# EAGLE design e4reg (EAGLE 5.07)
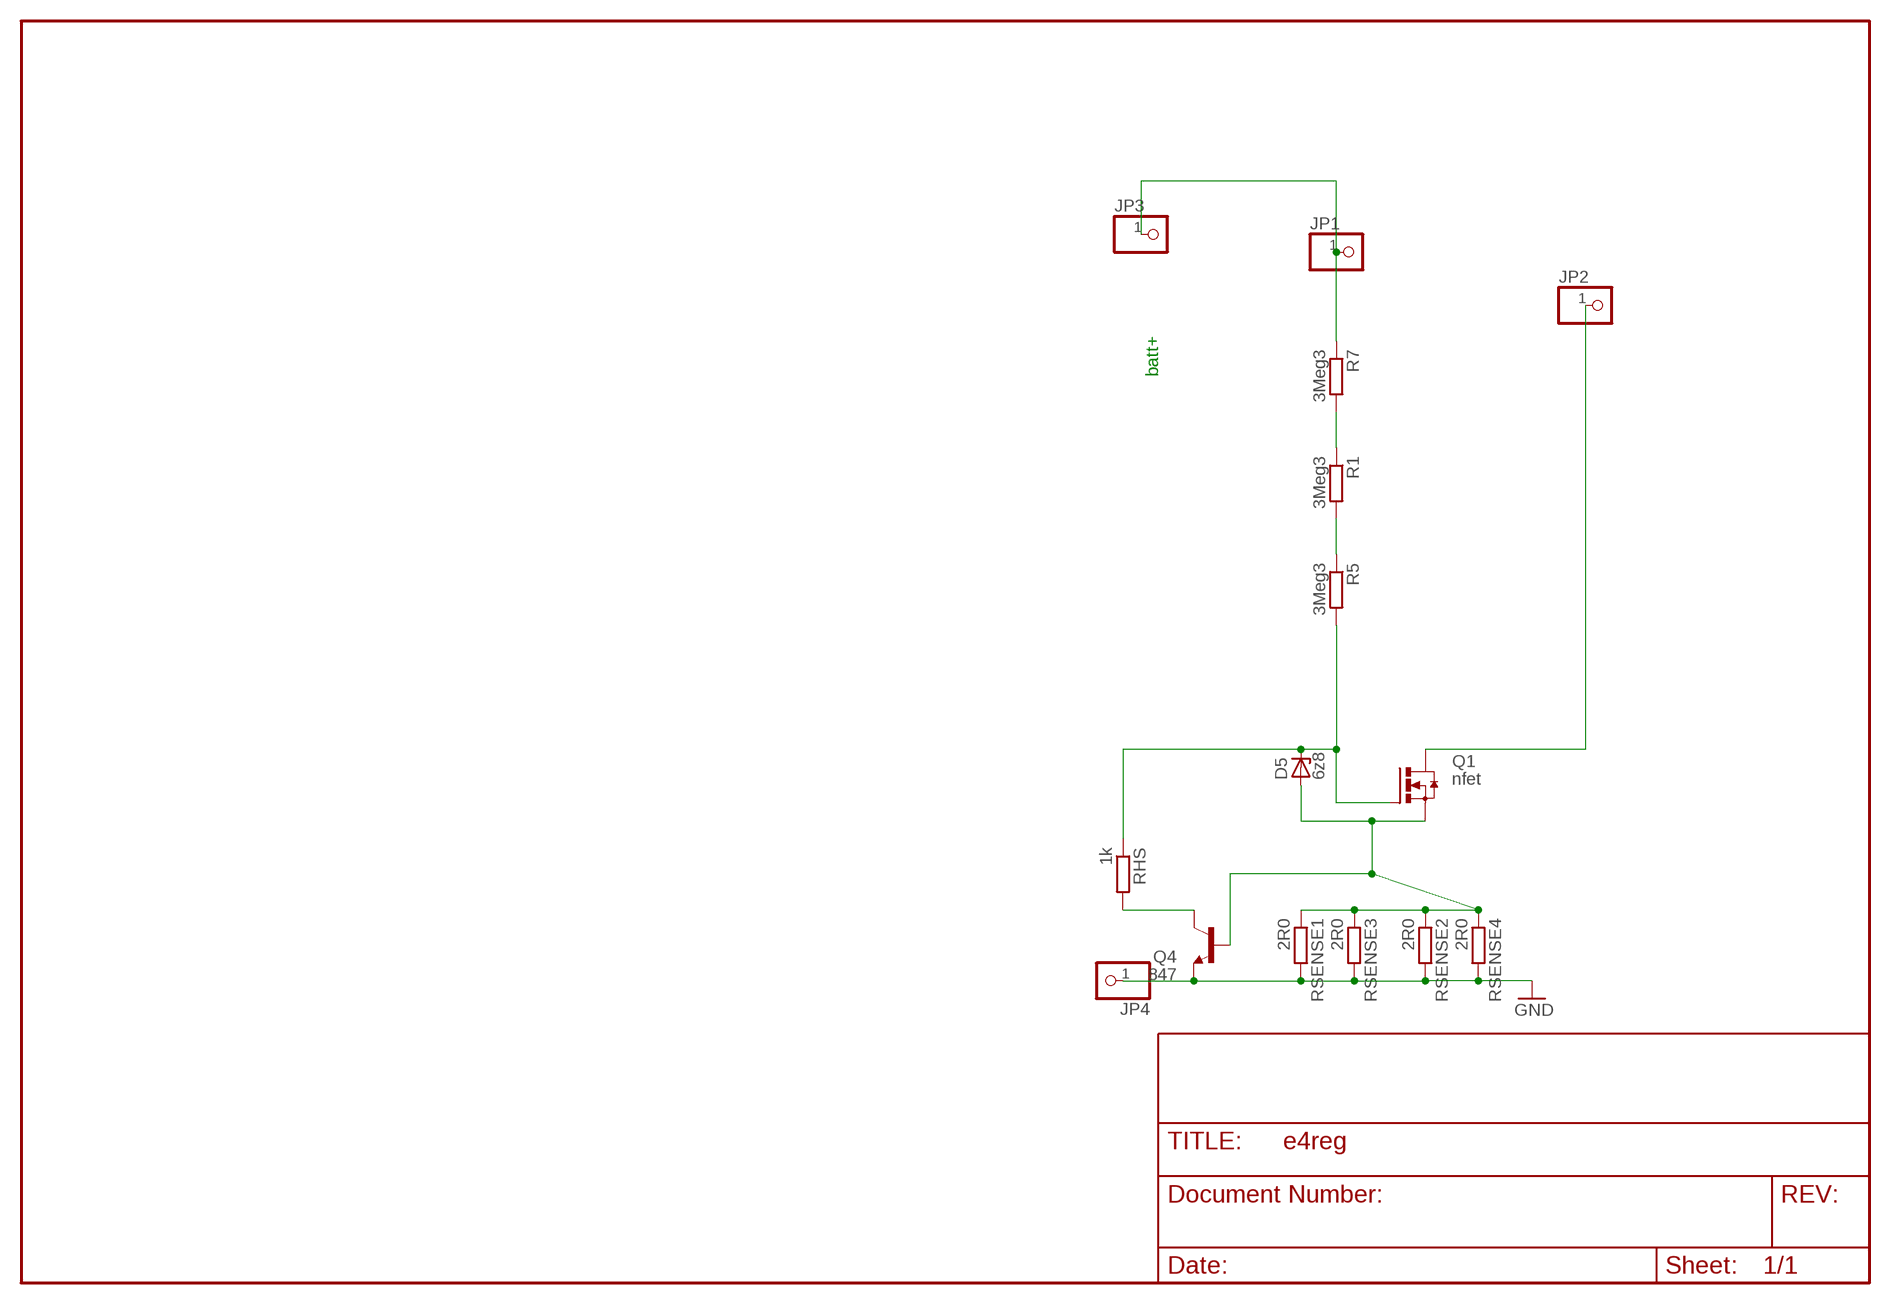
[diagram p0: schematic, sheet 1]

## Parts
D5  6z8  ZENER-DIODESOD80C  [SOD80C]
JP1  PINHD-1X11MM6  [1X1MM8]
JP2  PINHD-1X11MM6  [1X1MM8]
JP3  PINHD-1X11MM6  [1X1MM8]
JP4  PINHD-1X11MM6  [1X1MM8]
Q1  nfet  N-HEXFET_DPAK-  [TO252]
Q4  847  BC847ASMD  [SOT23]
R1  3Meg3  R-EU_R1206  [R1206]
R5  3Meg3  R-EU_R1206  [R1206]
R7  3Meg3  R-EU_R1206  [R1206]
RHS  1k  R-EU_R2512  [R2512]
RSENSE1  2R0  R-EU_R2512  [R2512]
RSENSE2  2R0  R-EU_R1210  [R1210]
RSENSE3  2R0  R-EU_R2512  [R2512]
RSENSE4  2R0  R-EU_R1210  [R1210]

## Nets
GND: JP4.1 Q4.2(E) RSENSE1.2 RSENSE2.2 RSENSE3.2 RSENSE4.2
LED-: JP2.1 Q1.3(D)
N$1: D5.C Q1.1(G) R5.2 RHS.1
N$2: R1.2 R5.1
N$4: R1.1 R7.2
N$7: Q4.3(C) RHS.2
S: D5.A Q1.2(S) Q4.1(B) RSENSE1.1 RSENSE2.1 RSENSE3.1 RSENSE4.1
VPLUS: JP1.1 JP3.1 R7.1

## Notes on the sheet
- batt+

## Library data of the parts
D5 = diode:ZENER-DIODE: Z-Diode
JP1-JP4 = pinhead:PINHD-1X1: PIN HEADER
Q1 = transistor-power:N-HEXFET_?-*: HEXFET® Power MOSFET
Q4 = transistor-npn:BC847*: NPN Transistor
R1 R5 R7 RHS RSENSE1-RSENSE4 = rcl:R-EU_: RESISTOR, European symbol

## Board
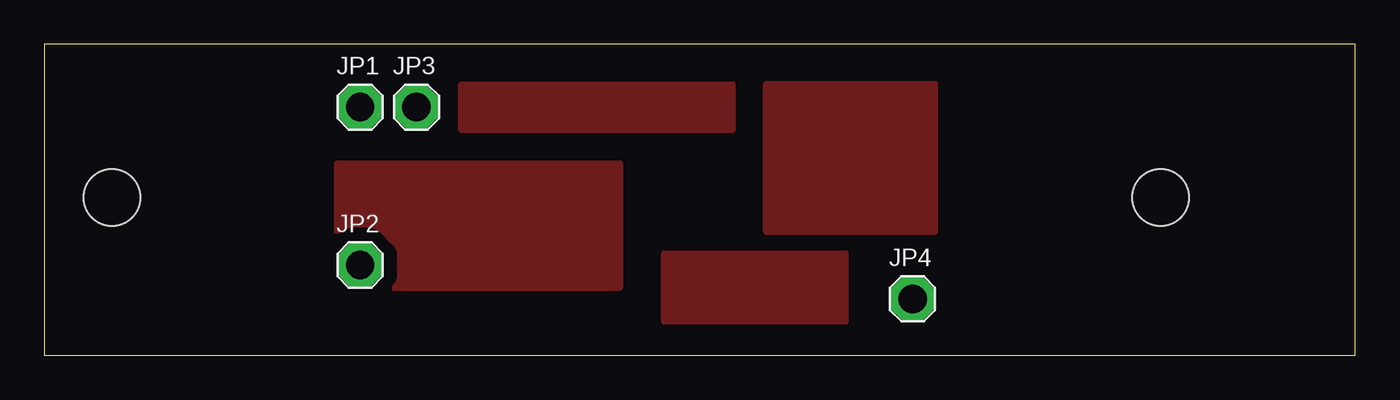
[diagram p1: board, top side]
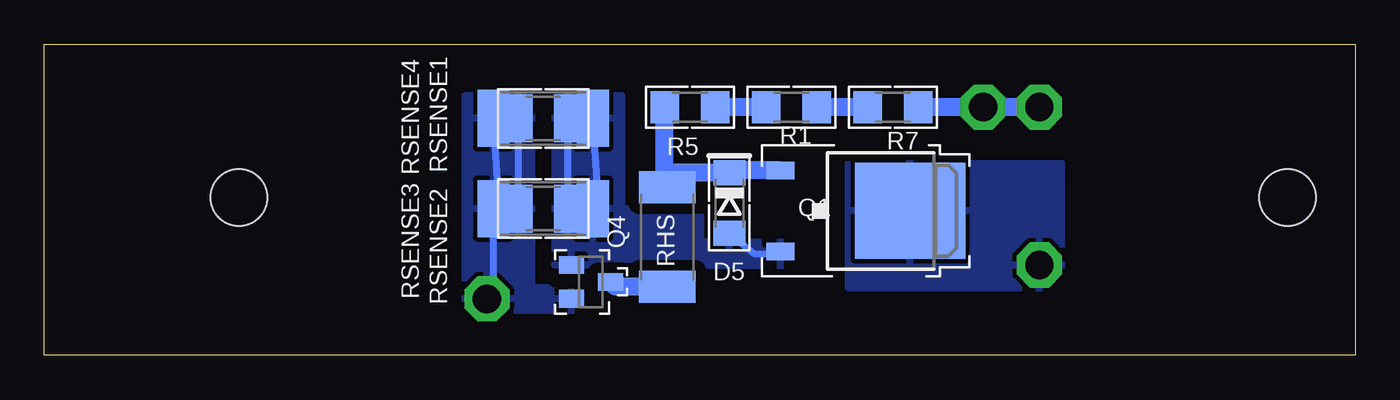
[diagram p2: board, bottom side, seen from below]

Size 73.81 x 17.5 mm. Coordinates in mm from the lower left corner, seen from the top.
Outline: 0,0 73.81,0 73.81,17.5 0,17.5 0,0
Copper layers (1*16): Top 0.035mm / dielectric 1.5mm / Bottom 0.035mm
Design rules "default *": minimum track width 10mil, minimum drill 24mil, track to track 8mil, track to pad 8mil, pad to pad 8mil, via to via 8mil, smd to smd 8mil, copper to edge 20mil, drill to drill 8mil, minimum pad ring 10mil, minimum via ring 8mil, stop-mask expansion 4mil, vias tented up to drill 0mil, thermal gap 10mil
Holes 3.2 mm at 62.87,8.89 3.81,8.89

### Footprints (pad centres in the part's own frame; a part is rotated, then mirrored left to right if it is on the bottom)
SOD80C = smd 1.4 x 1.8: A 1.7,0; C -1.7,0
1X1MM8 = drill 1.6 pad 2.54 octagon: 1 0,0
TO252 = smd 1 x 1.6: 1 -2.28,-3.53; 2 2.28,-3.53 | smd 5.4 x 6.2: 3 0,3.77
SOT23 = smd 1 x 1.4: 1 -0.95,-1.1; 2 0.95,-1.1; 3 0,1.1
R1206 = smd 1.6 x 1.803: 1 -1.422,0; 2 1.422,0
R2512 = smd 1.8 x 3.2: 1 -2.8,0; 2 2.8,0
R1210 = smd 1.6 x 2.7: 1 -1.4,0; 2 1.4,0

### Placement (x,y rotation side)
D5  35.24,8.57 270 bottom
JP1  17.78,13.97 0 top
JP2  17.78,5.08 0 top
JP3  20.95,13.97 0 top
JP4  48.9,3.17 0 top
Q1  28.83,8.13 270 bottom
Q4  43.03,4.13 270 bottom
R1  31.75,13.97 180 bottom
R5  37.47,13.97 180 bottom
R7  26.04,13.97 180 bottom
RHS  38.73,6.67 270 bottom
RSENSE1  45.72,13.34 180 bottom
RSENSE2  45.72,8.26 180 bottom
RSENSE3  45.72,8.26 180 bottom
RSENSE4  45.72,13.34 180 bottom

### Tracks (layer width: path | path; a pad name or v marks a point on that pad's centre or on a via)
GND
  Bottom 0.406: RSENSE2.2 RSENSE4.2 | RSENSE1.2 48.2,8.57 RSENSE3.2 48.52,3.55 JP4.1
  pour Bottom (isolate 0.813, rank 2): 46.35,14.61 50.16,14.61 50.16,2.54 43.81,2.54 43.81,3.81 46.35,3.81
LED-
  pour Bottom (isolate 0.813, rank 2): 16.51,10.79 28.57,10.79 28.57,3.81 16.51,3.81
N$1
  Bottom 1.016: 38.89,10.16 38.89,9.62 RHS.1 | 38.89,10.16 R5.2 | Q1.1 35.11,10.41 D5.C 38.77,10.27 38.89,10.16
N$2
  Bottom 1.016: R1.2 R5.1
N$3
  pour Top (isolate 0.813, rank 2): 34.92,5.71 45.09,5.71 45.09,1.91 34.92,1.91
N$4
  Bottom 1.016: R7.2 R1.1
N$5
  pour Top (isolate 0.813, rank 2): 40.64,15.24 40.64,6.99 50.16,6.99 50.16,15.24
N$6
  pour Top (isolate 0.813, rank 2): 16.51,10.79 32.38,10.79 32.38,3.81 16.51,3.81
N$7
  Bottom 0.406: RHS.2 38.58,3.49
  Bottom 1.016: RHS.2 41.67,3.87 Q4.3
N$8
  pour Top (isolate 0.813, rank 2): 23.5,15.24 38.73,15.24 38.73,12.7 23.5,12.7
S
  Bottom 0.406: Q1.2 32.89,5.85 | 33.02,5.71 33.86,5.71 D5.A | RSENSE1.1 42.6,8.57 RSENSE3.1 | RSENSE2.1 RSENSE4.1
  pour Bottom (isolate 0.61): 31.75,6.35 36.83,6.35 36.83,8.26 41.27,8.26 41.27,14.61 45.09,14.61 45.09,5.08 31.75,5.08
VPLUS
  Bottom 1.016: R7.1 JP3.1 JP1.1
